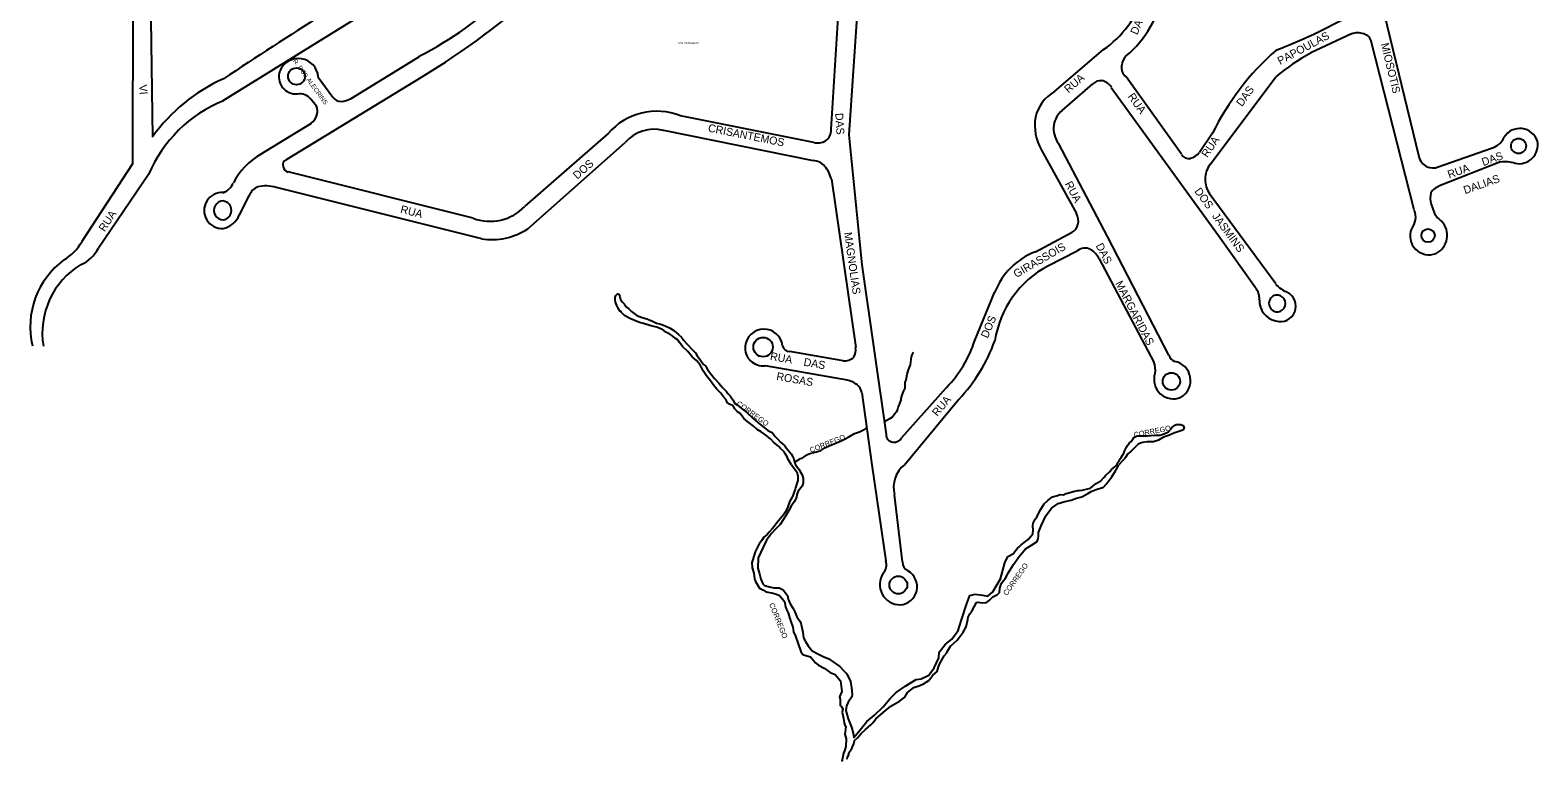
# Model space of a CAD drawing. Extents: x 325709 to 364434, y 7573432 to 7597073.
# Drawn here: x 347135 to 348281, y 7585777 to 7586333 of the extents above; entities that cross this region are included whole.
import ezdxf

# ---------------------------------------------------------------- set-up
doc = ezdxf.new("R2010")
doc.units = 0
for name, color, linetype in [('EDIFEXISTENT', 7, 'Continuous'), ('EDIFIDENTIF', 7, 'Continuous'), ('EDIFOBRAEXIS', 7, 'Continuous'), ('EDIFOBRAPROJ', 7, 'Continuous'), ('LIMITE_BAIRROS_MUNICIPIOS', 7, 'Continuous'), ('LOGRADOURO', 7, 'Continuous'), ('LOGRADOURO_TEXTO', 7, 'Continuous')]:
    doc.layers.add(name, color=color, linetype=linetype)

msp = doc.modelspace()

# ---------------------------------------------------------------- linework, layer by layer
at = {"layer": 'EDIFEXISTENT'}
for p, q in [((347784.4, 7586036.1), (347784.1, 7586035.6)), ((347769.8, 7586030.4), (347770.3, 7586030.3)), ((347770.5, 7586029), (347770.2, 7586028.6)), ((347770.3, 7586030.3), (347770.5, 7586029)), ((347784.1, 7586035.6), (347784.3, 7586034.2)), ((347784.3, 7586034.2), (347784.7, 7586033.9))]:
    msp.add_line(p, q, dxfattribs=at)
at = {"layer": 'EDIFOBRAEXIS'}
for points in [[(347713.3, 7586001.9), (347712, 7586003.9), (347710.4, 7586006.5), (347710, 7586007.9), (347708.8, 7586010), (347707.7, 7586011.8), (347704.9, 7586014.2), (347703.6, 7586015.8), (347702.1, 7586017), (347700.1, 7586018.6), (347697.3, 7586021.6), (347693.8, 7586024.3), (347690.2, 7586027), (347687.3, 7586028.7), (347684.1, 7586031.4), (347680.1, 7586034.5), (347677.2, 7586037.1), (347674.4, 7586040.9), (347672.3, 7586042.1), (347670.2, 7586044.4), (347669, 7586046.8), (347666.2, 7586048), (347664.5, 7586049.3), (347663.7, 7586051.3), (347661.6, 7586053.6), (347659.3, 7586056.6), (347656.5, 7586059.4), (347654.3, 7586062.2), (347651.7, 7586065.6), (347648.6, 7586069.4), (347646.1, 7586073.4), (347643.8, 7586077.9), (347641.1, 7586081.3), (347637.8, 7586084.1), (347634.6, 7586088), (347630.8, 7586091.7), (347628.1, 7586094.9), (347627.1, 7586096.6), (347625.2, 7586098), (347623, 7586099.6), (347620.7, 7586101.1), (347617.9, 7586102.8), (347616.3, 7586103.9), (347614.4, 7586104.9), (347610.9, 7586106.6), (347607.4, 7586107.4), (347604.9, 7586108.1), (347600.7, 7586109.4), (347597.7, 7586110.2), (347593.4, 7586112), (347590.4, 7586113.1), (347586.4, 7586115.4), (347584.8, 7586116.9), (347583.8, 7586118), (347583.5, 7586118.6), (347582.9, 7586118.8), (347582.3, 7586119.7), (347581.4, 7586121.5), (347580.5, 7586123), (347580, 7586124.3), (347579.5, 7586125.6), (347579.2, 7586127.7), (347579.2, 7586129.3), (347579.8, 7586130.7), (347580.3, 7586131.2), (347581, 7586132), (347582, 7586131.6), (347582.9, 7586129.8), (347583.3, 7586127.6), (347584.5, 7586125.8), (347585.3, 7586125), (347586.3, 7586124), (347586.4, 7586123.8), (347588, 7586121.8), (347589.6, 7586120.6), (347591.8, 7586118.5), (347595.7, 7586115.4), (347599.8, 7586113.8), (347603.4, 7586112.9), (347605.9, 7586111.9), (347607.7, 7586111), (347610.6, 7586109.7), (347614.1, 7586108.8), (347617.3, 7586107.5), (347621.1, 7586105.7), (347623.8, 7586103.9), (347625.8, 7586102.3), (347627.4, 7586100.9), (347629.7, 7586099), (347631.4, 7586096.3), (347634.1, 7586093.6), (347638.1, 7586089.3), (347640.4, 7586086.9), (347641.7, 7586084.7), (347643.7, 7586082.3), (347646.4, 7586078.1), (347647.9, 7586077.2), (347649.5, 7586074.4), (347652, 7586071.1), (347654.7, 7586067.5), (347658, 7586063.9), (347659.5, 7586062.2), (347660.8, 7586060.6), (347663.9, 7586057.7), (347665, 7586056.2), (347666.6, 7586054.3), (347667.7, 7586052.8), (347668.9, 7586050.9), (347669.9, 7586048.7), (347671.9, 7586047.4), (347675, 7586044.9), (347679.3, 7586041.6), (347683.8, 7586037.4), (347687.7, 7586034.1), (347690.2, 7586032.1), (347693.9, 7586029.1), (347695, 7586028.3), (347696.9, 7586027.2), (347698.6, 7586026.4), (347701, 7586023.4), (347702.9, 7586021.4), (347704.9, 7586019), (347706.4, 7586017.7), (347708.2, 7586016.3), (347709.3, 7586014.8), (347711.8, 7586011.7), (347713.1, 7586010.3), (347714.4, 7586008), (347715.2, 7586006.4), (347715.3, 7586005.1), (347715.5, 7586003.8), (347716.3, 7586001.9)], [(347784.2, 7586035), (347788.6, 7586037.4), (347789.9, 7586038), (347791.1, 7586039.8), (347792, 7586041), (347793.1, 7586042.2), (347793.9, 7586043.4), (347794.5, 7586045.4), (347794.9, 7586046.7), (347795.5, 7586047.8), (347795.8, 7586049.3), (347796.7, 7586051.1), (347796.8, 7586052.3), (347797.3, 7586054.1), (347797.8, 7586055.7), (347798.5, 7586057.5), (347799.6, 7586060.1), (347799.7, 7586061.8), (347799.7, 7586064.5), (347800.4, 7586066.6), (347801.2, 7586070.9), (347802.3, 7586074.2), (347803.7, 7586077.9), (347804.6, 7586083.9), (347805.2, 7586086), (347806, 7586087.6)], [(347715.5, 7586003.8), (347716.9, 7586004.7), (347718, 7586005.4), (347719.4, 7586006.2), (347720.1, 7586006.6), (347721.3, 7586007), (347723, 7586007.8), (347725.6, 7586009.7), (347728.1, 7586010.7), (347730.3, 7586011.2), (347732.3, 7586011.6), (347735.5, 7586012.8), (347738.7, 7586014.7), (347742.4, 7586016.6), (347744.6, 7586017.4), (347751, 7586020), (347754.1, 7586021.7), (347756.8, 7586023.2), (347761.1, 7586025.7), (347765, 7586026.9), (347767.5, 7586028.2), (347770.3, 7586029.7)], [(347960.6, 7586001.9), (347961.7, 7586003.8), (347962.1, 7586004.4), (347962.4, 7586004.9), (347962.9, 7586005.8), (347963.2, 7586006.3), (347963.9, 7586007.4), (347964.8, 7586008.7), (347965.5, 7586010), (347966, 7586010.8), (347966.5, 7586012.1), (347967.8, 7586014.7), (347968.7, 7586016.4), (347970.1, 7586018.3), (347971.5, 7586019.6), (347973, 7586021.9), (347973.4, 7586022.4), (347974.6, 7586023.2), (347976.2, 7586023.8), (347979.3, 7586023.9), (347982.4, 7586023.8), (347984, 7586024), (347989.5, 7586024.4), (347993.5, 7586024.5), (347997, 7586025.7), (347999.8, 7586027), (348002.2, 7586029.5), (348002.8, 7586030.6), (348003.5, 7586031.1), (348004.1, 7586031.7), (348005.6, 7586032.5), (348009.3, 7586032.6), (348011.1, 7586031.7), (348011.8, 7586029.9), (348010.8, 7586028.2), (348007.7, 7586027.2), (348004, 7586025.8), (348000.7, 7586024.4), (347996, 7586022.8), (347992.4, 7586020.5), (347990.1, 7586019.8), (347988.4, 7586019.4), (347985.9, 7586019.4), (347983.7, 7586019.2), (347980.5, 7586018.7), (347978.5, 7586018.2), (347976.9, 7586017.6), (347974.1, 7586014.8), (347971.4, 7586012.3), (347969.1, 7586010.1), (347968.4, 7586009.3), (347967.1, 7586007.5), (347966.6, 7586006.7), (347965, 7586004.8), (347965, 7586004.8), (347962.2, 7586001.9)], [(347713.3, 7586001.9), (347717.3, 7585996.6), (347717.9, 7585994.4), (347718.2, 7585993.1), (347718.2, 7585989.9), (347717.1, 7585986.9), (347716.3, 7585984.4), (347716.1, 7585983.2), (347715.1, 7585980.4), (347714.6, 7585978.9), (347713.6, 7585976.8), (347711.8, 7585973.7), (347710.6, 7585969.8), (347708.7, 7585966.1), (347707.2, 7585963.8), (347702.2, 7585957.6), (347700.1, 7585954.8), (347698.5, 7585953.2), (347696.3, 7585950.7), (347694.7, 7585948.8), (347692.2, 7585946.7), (347690.4, 7585944.1), (347688.7, 7585941.8), (347687.4, 7585939.1), (347685.6, 7585935.7), (347683.9, 7585929.8), (347683.2, 7585927.6), (347683.5, 7585923.5), (347684.8, 7585919.5), (347685.2, 7585915.1), (347686, 7585913), (347689.1, 7585908.1), (347690.5, 7585907.2), (347691.9, 7585906.5), (347693.5, 7585905.4), (347695.3, 7585904.9), (347698.4, 7585904.4), (347701.9, 7585903.4), (347704.1, 7585902.5), (347706, 7585900.5), (347707.9, 7585897.8), (347708.8, 7585893.9), (347709.5, 7585891.8), (347710.8, 7585889.3), (347711.8, 7585885.7), (347712.5, 7585883.4), (347714.3, 7585878.4), (347714.9, 7585874.8), (347716.3, 7585871.4), (347718.4, 7585865.7), (347720.5, 7585859.9), (347722, 7585857.6), (347722.6, 7585857.2), (347724.9, 7585856.4), (347727.8, 7585855.8), (347731.5, 7585851.3), (347733.8, 7585849.5), (347738.1, 7585847.1), (347742.8, 7585843.8), (347746.4, 7585842.2), (347750.6, 7585837.6), (347751.6, 7585829.4), (347749.9, 7585825.4), (347750.4, 7585823.6), (347750.4, 7585818.8), (347751.1, 7585818.1), (347752.4, 7585816.3), (347751.8, 7585813.7), (347752.9, 7585808.9), (347753.4, 7585805.6), (347753.8, 7585803.7), (347754.5, 7585802.5), (347753.8, 7585796.8), (347754.8, 7585793.4), (347754.5, 7585787.6), (347753.6, 7585784.2), (347752.9, 7585782.5), (347752.4, 7585779.7), (347751.6, 7585776.6), (347752.3, 7585777.6)], [(347716.3, 7586001.9), (347719, 7585998.5), (347720, 7585996.7), (347721.4, 7585994.3), (347722.2, 7585991.3), (347722.1, 7585988), (347721.3, 7585985.7), (347718.3, 7585981.7), (347717.3, 7585979.2), (347717, 7585976.9), (347715.3, 7585973.6), (347713, 7585970.3), (347711.4, 7585967), (347709.4, 7585964.1), (347707, 7585960), (347704.7, 7585956.4), (347703.3, 7585954.8), (347701.1, 7585952.8), (347698, 7585949.7), (347694.2, 7585944.4), (347692.1, 7585939.7), (347689.9, 7585935.5), (347688, 7585931), (347687.8, 7585923.1), (347688.9, 7585919), (347690.1, 7585914.9), (347691.5, 7585911.3), (347692.8, 7585910.1), (347696.5, 7585909), (347699.9, 7585908.2), (347704, 7585908.2), (347707, 7585906.6), (347710.2, 7585902.3), (347710.8, 7585899.7), (347712.2, 7585896.1), (347714.5, 7585892.6), (347715.9, 7585890), (347717.4, 7585886.1), (347719.9, 7585882.6), (347720.6, 7585880.4), (347721.8, 7585874.6), (347722.5, 7585870.1), (347723.9, 7585867.5), (347726, 7585864), (347729, 7585860.4), (347733.8, 7585857.7), (347737.5, 7585855.9), (347741.7, 7585854.2), (347746, 7585851.3), (347750, 7585848.4), (347752.5, 7585845.5), (347755.4, 7585842.9), (347758.1, 7585837), (347759, 7585832.2), (347759.4, 7585827.4), (347759.1, 7585825.3), (347756.4, 7585821.2), (347755.1, 7585818.6), (347754.7, 7585814.9), (347756.3, 7585808.6), (347758.9, 7585802.3), (347760.3, 7585797.6), (347760.6, 7585794.3), (347765.4, 7585800.3), (347770.7, 7585806.6), (347776.3, 7585811.5), (347782.9, 7585817.8), (347788.1, 7585823.8), (347792.9, 7585828.5), (347800.2, 7585833.6), (347808.1, 7585838.5), (347811.9, 7585839), (347817.6, 7585841.8), (347821.8, 7585847.5), (347825.2, 7585855.1), (347825.6, 7585859.3), (347830.4, 7585865.3), (347835.1, 7585869.3), (347840.1, 7585875.7), (347842.6, 7585883.8), (347846.6, 7585896.4), (347848.9, 7585902.4), (347852.9, 7585903.4), (347858.5, 7585902.6), (347862.5, 7585901.8), (347866.3, 7585905.3), (347872.3, 7585915.2), (347875.6, 7585927.3), (347877.8, 7585932.1), (347882, 7585934.3), (347883, 7585935.8), (347884, 7585937.2), (347885, 7585938.4), (347886.3, 7585939.5), (347887.8, 7585940.9), (347891.3, 7585943.4), (347893.2, 7585945.1), (347896.7, 7585949.3), (347896.9, 7585952.2), (347896.7, 7585955.4), (347897.1, 7585957.5), (347898.6, 7585960.6), (347899.9, 7585962.1), (347902.2, 7585966.9), (347905.5, 7585972.2), (347908.3, 7585974.9), (347911.6, 7585977.6), (347915.5, 7585978.6), (347917.6, 7585979.2), (347920.2, 7585979.1), (347921.8, 7585980), (347923, 7585980.3), (347925.9, 7585981), (347927.5, 7585981.6), (347931.1, 7585982.3), (347931.9, 7585982.2), (347934.3, 7585982.6), (347940.5, 7585984), (347942.6, 7585985.8), (347945, 7585987.7), (347948.5, 7585989.6), (347950.7, 7585992.2), (347952.3, 7585993.9), (347955.1, 7585996.5), (347956.5, 7585998.2), (347958.2, 7585999.5), (347959.1, 7586000.2), (347959.1, 7586000.2)], [(347755.7, 7585777.9), (347755.9, 7585779.5), (347756.8, 7585781.3), (347757, 7585782.6), (347757.8, 7585784.2), (347758.8, 7585785.4), (347759.5, 7585786.4), (347759.8, 7585787.3), (347760.8, 7585789.6), (347761.1, 7585792.2), (347763.4, 7585794.1), (347766, 7585797.2), (347769.5, 7585800.4), (347773.7, 7585804), (347775.3, 7585805.7), (347777.3, 7585808.6), (347783.1, 7585813.5), (347788.7, 7585818.1), (347795.5, 7585822.1), (347799.4, 7585825.1), (347801.4, 7585828.6), (347806.3, 7585832.4), (347810.9, 7585834), (347813.7, 7585835.2), (347817.7, 7585837.7), (347820.7, 7585841.9), (347824.1, 7585844.5), (347825.1, 7585848.1), (347826.1, 7585850.8), (347829.3, 7585856.6), (347831.3, 7585858.9), (347831.9, 7585860), (347834.2, 7585863.8), (347839.3, 7585868.4), (347843.8, 7585874.4), (347846.2, 7585878.6), (347847.3, 7585884.1), (347847.6, 7585886), (347849, 7585888.5), (347850.4, 7585890.6), (347853.9, 7585897.2), (347855.3, 7585897.3), (347858.3, 7585896.8), (347861.6, 7585897), (347863.5, 7585898.7), (347866.3, 7585901.3), (347869.8, 7585903.1), (347871.5, 7585904.7), (347871.8, 7585907.9), (347873, 7585911.9), (347876.1, 7585915.6), (347878.3, 7585920), (347882.1, 7585925.9), (347886.5, 7585932.1), (347891.1, 7585938), (347895.8, 7585940.8), (347900, 7585943.4), (347900.9, 7585945.8), (347901.2, 7585947.2), (347901.2, 7585950.3), (347903, 7585955.5), (347904.9, 7585959.1), (347906.7, 7585963.1), (347910.9, 7585968.9), (347915.9, 7585972.4), (347921.1, 7585973.9), (347925.9, 7585975), (347930, 7585976.5), (347934, 7585977.6), (347936.8, 7585979), (347938.6, 7585980.1), (347941.2, 7585981.5), (347944.2, 7585982.9), (347950.4, 7585984.8), (347952.5, 7585987.1), (347954, 7585989.1), (347956.8, 7585992.6), (347959.5, 7585997.2), (347960.2, 7585998.3), (347960.6, 7585999.1), (347962.2, 7586001.9)], [(347959.1, 7586000.2), (347959.4, 7586000.6), (347959.4, 7586000.6), (347960.6, 7586001.9)]]:
    msp.add_lwpolyline(points, dxfattribs=at)
msp.add_arc((348082.4, 7586124.6), 6.37, 260.7721, 99.2279, dxfattribs=at)
at = {"layer": 'EDIFOBRAPROJ'}
for centre, radius in [((347337.1, 7586297.4), 6.43), ((348266, 7586244.4), 5.74), ((348197.2, 7586176.2), 5.07), ((347691.7, 7586091.4), 7.37), ((348002.1, 7586065.3), 6.62), ((347794.5, 7585910.4), 6.75)]:
    msp.add_circle(centre, radius, dxfattribs=at)
for centre, radius, start, end in [((347281.4, 7586195.4), 7.14, 89.782, 270.218), ((347280.4, 7586195.4), 7.2, 277.6426, 82.3574), ((348082.7, 7586124.6), 6.44, 102.139, 257.861)]:
    msp.add_arc(centre, radius, start, end, dxfattribs=at)
at = {"layer": 'LOGRADOURO'}
for p, q in [((347753.3, 7586418.5), (347743.3, 7586257)), ((347225.5, 7586399.2), (347227.5, 7586251.2)), ((347281.4, 7586278.9), (347380.9, 7586340.7)), ((348138.9, 7586329.6), (348108.2, 7586315.2)), ((348186.7, 7586195.7), (348154.3, 7586323.1)), ((347378.6, 7586280.5), (347430.4, 7586312.5)), ((347913.3, 7586285.9), (347950.5, 7586317.8)), ((347329.3, 7586234.1), (347432.1, 7586296.8)), ((347353.6, 7586296.8), (347364.6, 7586281.6)), ((347919.1, 7586271.3), (347942.4, 7586291.7)), ((348009.9, 7586238.1), (347967.7, 7586296.9)), ((348031.5, 7586230.2), (348081.4, 7586297)), ((347352.2, 7586274.7), (347348, 7586280)), ((347730.2, 7586247.1), (347629, 7586267.2)), ((347309.5, 7586238), (347348.3, 7586261.7)), ((347573.9, 7586253.8), (347510.6, 7586198.5)), ((347616.1, 7586256.3), (347729.9, 7586233.3)), ((348033.4, 7586254.1), (348023.4, 7586239.3)), ((347512.9, 7586181.4), (347586.9, 7586247)), ((348205, 7586228.4), (348245.4, 7586242.6)), ((347903.3, 7586241.3), (347929.9, 7586192.9)), ((348252.4, 7586232.2), (348206, 7586214.1)), ((347212.4, 7586230.7), (347173.9, 7586171.8)), ((347224.5, 7586222.7), (347186.4, 7586166.7)), ((347471.2, 7586189.4), (347330.6, 7586224.6)), ((347321.5, 7586213), (347477.6, 7586173.9)), ((347743.6, 7586219.1), (347762.1, 7586091)), ((348081.4, 7586139.4), (348030.9, 7586208.2)), ((347293.6, 7586191.7), (347301, 7586206.7)), ((348199.5, 7586200), (348202, 7586193)), ((347898.7, 7586163.9), (347926.6, 7586178.7)), ((347908.2, 7586153.1), (347930.5, 7586164.6)), ((347947.2, 7586158.5), (347988.7, 7586080)), ((347852.6, 7586096.5), (347867.7, 7586132.9)), ((347752.6, 7586081), (347712, 7586088)), ((347693.4, 7586077.3), (347755.6, 7586066.4)), ((347797.1, 7586022.5), (347831.1, 7586060.7)), ((347766.8, 7586056.7), (347774.5, 7586001.9)), ((347799.2, 7586001.9), (347840.5, 7586051.7)), ((347774.5, 7586001.9), (347785, 7585928.8)), ((347797.7, 7585928), (347791.6, 7585979.1))]:
    msp.add_line(p, q, dxfattribs=at)
for points in [[(347211, 7586501.9), (347212.7, 7586357.7), (347212.4, 7586230.7)], [(348127, 7586493), (348166.2, 7586335.5), (348190.2, 7586236.5)], [(347767.9, 7586413.7), (347756.9, 7586252.8), (347766.7, 7586154), (347785.3, 7586025)], [(347956.4, 7586289), (348037.8, 7586176.3), (348066, 7586136.6)], [(348000.2, 7586085.2), (347953.5, 7586175.6), (347916.5, 7586246)]]:
    msp.add_lwpolyline(points, dxfattribs=at)
for centre, radius, start, end in [((349384.8, 7583138.6), 3793.4, 120.9609, 123.6747), ((347280.9, 7586596.9), 321.2, 297.7332, 312.3851), ((347126.2, 7586804), 592.3, 301.0953, 312.1432), ((347906.9, 7586381.6), 77.3, 304.3629, 342.6173), ((347912, 7586378.3), 85.9, 310.4786, 348.5812), ((347911.1, 7586755.8), 470.5, 291.2192, 298.8732), ((348143.7, 7586318.2), 12.3, 68.012, 112.9003), ((348146.2, 7586321.8), 8.19, 9.6277, 74.954), ((347975.6, 7586304.7), 11.3, 133.4128, 174.2629), ((348219.5, 7586162.1), 207.6, 131.7067, 153.7127), ((348189.2, 7586166.6), 169.2, 118.5705, 129.564), ((347336.4, 7586296.8), 12.8, 158.9006, 276.2112), ((347338.4, 7586295.7), 15.2, 4.2895, 157.8573), ((347973.5, 7586304.2), 9.37, 169.9942, 231.2297), ((347337.1, 7586172.9), 134.7, 114.4228, 144.4377), ((347948.4, 7586285.4), 8.69, 85.7753, 133.7599), ((347947.6, 7586284), 10.2, 29.848, 81.7039), ((347321.3, 7586181.6), 105.1, 112.2869, 156.9973), ((347339.7, 7586273.8), 10.3, 36.726, 100.763), ((347370.8, 7586285.7), 7.42, 213.7808, 272.1063), ((347370.3, 7586294.4), 16.1, 272.4612, 300.7664), ((347928.8, 7586259.1), 30.9, 120.2254, 166.6073), ((347342.1, 7586270.4), 10.7, 305.3426, 347.6409), ((347344.9, 7586271), 8.11, 339.3147, 26.7604), ((347610.7, 7586222.5), 48.3, 67.7262, 139.5707), ((347936.9, 7586260.3), 38.6, 171.081, 209.4427), ((347930.4, 7586257.5), 17.9, 129.1981, 171.0432), ((347608.9, 7586228.2), 28.9, 75.6595, 139.657), ((347733.9, 7586256.2), 9.49, 304.0762, 4.8343), ((347931.5, 7586257.6), 19, 171.838, 217.5941), ((348267, 7586243.7), 14, 17.7028, 148.6327), ((347733.3, 7586258.6), 11.9, 255.1319, 299.7593), ((348241.1, 7586257.4), 15.4, 286.2765, 335.314), ((348266.4, 7586245.1), 14.2, 257.8822, 11.5585), ((347336.7, 7586191.8), 53.6, 120.4471, 152.845), ((347331, 7586230), 4.44, 112.3147, 198.8209), ((347729, 7586220.6), 12.7, 42.0934, 86.1283), ((348015, 7586240.4), 5.63, 205.0717, 285.4371), ((348013.7, 7586247), 12.3, 283.1756, 321.4844), ((348201.4, 7586239), 11.5, 192.4722, 243.9201), ((348255.8, 7586208.9), 23.5, 71.0353, 98.3727), ((347332, 7586229.7), 5.32, 192.5742, 255.1408), ((347722, 7586214.3), 22.1, 12.4293, 41.9493), ((348044.9, 7586219.4), 17.2, 141.1082, 181.1302), ((348200.9, 7586240.1), 12.4, 248.0925, 289.2891), ((347280.5, 7586195.3), 13.7, 86.0658, 273.9342), ((347276.4, 7586221.6), 13.7, 291.3073, 336.7825), ((347312.1, 7586202.4), 11.8, 112.4566, 158.6845), ((347313.8, 7586186.7), 27.3, 73.7301, 103.2829), ((348049.3, 7586219.6), 21.6, 181.3983, 211.8848), ((348217.1, 7586204.7), 18.2, 166.8256, 194.8791), ((348211.1, 7586200.8), 14.2, 111.0373, 145.761), ((347484, 7586224), 36.9, 249.7309, 316.2063), ((347277.8, 7586198.4), 17.1, 282.0827, 337.1131), ((347919.7, 7586187.3), 11.7, 346.7251, 28.6445), ((348173.8, 7586190.4), 14, 319.8918, 22.1006), ((348218.5, 7586202.9), 19.2, 210.8432, 234.8149), ((348196.4, 7586176.4), 15.4, 296.4852, 44.1159), ((347485.7, 7586222.8), 49.6, 260.5816, 303.333), ((347922.9, 7586186.1), 8.27, 296.7572, 349.4659), ((348198, 7586176.1), 14.5, 158.6302, 291.3721), ((347139.8, 7586191.4), 39.4, 301.2474, 330.1961), ((347162.7, 7586178.3), 26.4, 293.574, 334.0081), ((347918.2, 7586113.4), 54.1, 111.0967, 158.881), ((347936.4, 7586157.5), 9.2, 63.4283, 129.5862), ((347932.3, 7586151.4), 16.5, 25.3907, 60.3829), ((347198, 7586106.8), 63.4, 126.5603, 193.1943), ((347204.4, 7586102.2), 60.6, 121.0116, 189.6393), ((347944.4, 7586084.7), 77.3, 117.9034, 171.4895), ((348098.7, 7586154.4), 22.9, 221.0765, 248.3379), ((348056.6, 7586128.4), 12.4, 354.5588, 41.4404), ((348084.9, 7586122.6), 11.8, 252.9866, 63.0975), ((348084.8, 7586126.7), 15.8, 177.8787, 257.569), ((347692.3, 7586090.8), 14.3, 6.4321, 174.8764), ((347766.5, 7586123.9), 90.4, 315.6257, 342.3129), ((347746.9, 7586140), 128.7, 316.6457, 340.066), ((347691.7, 7586090.8), 13.7, 174.6851, 277.1752), ((347712.4, 7586094.1), 6.15, 196.0676, 266.6505), ((347753.5, 7586091.4), 10.5, 264.7099, 313.7118), ((347751.5, 7586089.2), 10.7, 329.8645, 9.5122), ((348007.8, 7586087.8), 8.02, 199.0088, 247.5583), ((347975.1, 7586074.1), 14.8, 349.1849, 23.7069), ((348003.6, 7586066.7), 14.7, 161.9677, 293.2145), ((348002, 7586066), 14.7, 300.2805, 79.0185), ((347749.9, 7586044.4), 22.7, 53.6159, 75.2371), ((347757.2, 7586055.2), 9.68, 9.3976, 51.0193), ((347790.8, 7586024.6), 5.46, 175.2919, 264.8801), ((347791.2, 7586025.7), 6.67, 262.1635, 331.1663), ((347812.8, 7585984.8), 21.9, 128.5212, 194.9581), ((347775.9, 7585925.7), 9.55, 318.8928, 18.5527), ((347805, 7585927.6), 7.23, 177.1603, 243.6317), ((347795.8, 7585910.8), 15.4, 145.7891, 270.4416), ((347795, 7585909.1), 13.8, 274.1293, 60.4582)]:
    msp.add_arc(centre, radius, start, end, dxfattribs=at)

# ---------------------------------------------------------------- texts
at = {"layer": 'EDIFIDENTIF'}
for rotation, p in [(324.0975, (347671.1, 7586047.6)), (10.8772, (347973.9, 7586022.6)), (21.7808, (347728.1, 7586010.9)), (54.9796, (347877.1, 7585902)), (292.052, (347696.2, 7585895.8))]:
    msp.add_text('CORREGO', height=4, rotation=rotation, dxfattribs=at).set_placement(p)
at = {"layer": 'LIMITE_BAIRROS_MUNICIPIOS'}
msp.add_text('DOS PASSAROS', height=1.5, dxfattribs=at).set_placement((347626.5, 7586321.9))
at = {"layer": 'LOGRADOURO_TEXTO'}
for s, height, rotation, p in [('DAS', 6, 66.5173, (347976.1, 7586328.5)), ('PAPOULAS', 6, 28.1779, (348084.7, 7586306)), ('MIOSOTIS', 6, 283.6015, (348161.3, 7586322)), ('R. DOS ALECRINS', 3.431, 305.8294, (347334.1, 7586309)), ('VI', 6, 274.9543, (347217.3, 7586290.8)), ('RUA', 6, 40.645, (347923.8, 7586284.3)), ('DAS', 6, 54.596, (348055.8, 7586273.9)), ('RUA', 6, 305.678, (347968.6, 7586282)), ('DAS', 6, 273.4359, (347746.6, 7586269.3)), ('CRISANTEMOS', 6, 348.7808, (347649.5, 7586255.4)), ('RUA', 6, 55.7797, (348029.4, 7586235.1)), ('DOS', 6, 41.1805, (347550.4, 7586218.7)), ('DAS', 6, 19.3689, (348239.2, 7586229.1)), ('RUA', 6, 19.3689, (348213.3, 7586219.6)), ('DALIAS', 6, 19.3689, (348225.4, 7586207.7)), ('RUA', 6, 297.7947, (347920.9, 7586215.6)), ('DOS', 6, 306.2416, (348019.3, 7586209.9)), ('RUA', 6, 345.9553, (347415.6, 7586193.6)), ('RUA', 6, 56.9336, (347191.2, 7586178.7)), ('JASMINS', 6, 306.2416, (348032.7, 7586190.9)), ('MAGNOLIAS', 6, 278.2028, (347753.2, 7586178.4)), ('GIRASSOIS', 6, 30.0647, (347884.2, 7586143.9)), ('DAS', 6, 297.3341, (347944.4, 7586168.6)), ('MARGARIDAS', 6, 297.3341, (347959.2, 7586139.9)), ('DOS', 6, 67.4826, (347862.5, 7586097.7)), ('RUA', 6, 350.1706, (347696.7, 7586081.7)), ('DAS', 6, 350.1706, (347722.2, 7586077.3)), ('ROSAS', 6, 350.1706, (347701.5, 7586066.4)), ('RUA', 6, 50.2726, (347824.2, 7586038.2))]:
    msp.add_text(s, height=height, rotation=rotation, dxfattribs=at).set_placement(p)

doc.saveas('drawing.dxf')
